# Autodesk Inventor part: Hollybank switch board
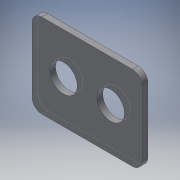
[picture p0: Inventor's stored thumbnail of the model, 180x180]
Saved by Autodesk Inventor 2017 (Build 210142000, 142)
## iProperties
Created: 2015-12
Part Number: Hollybank switch board
Material: Generic
Document SubType Name: Modeling
Designer: Designer
Density: 1 g/cm^3
Appearance: Default
Author: Designer
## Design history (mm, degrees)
sketch "Sketch1"
  geometry: L1 (-57, 68.367)-(23, 68.367); L2 (33, 58.367)-(33, -21.633); L3 (23, -31.633)-(-57, -31.633); L4 (-67, -21.633)-(-67, 58.367); L5 (-5, -5)-(-5, 5.367); L6 (-2, 8.367)-(5, 8.367); L7 (8, 11.367)-(8, 33.367); L8 (-39.45, 36.367)-(5, 36.367); L9 (-36.434, 15.879)-(-43.759, 10.649); L10 (-36.443, 20.769)-(-43.792, 25.973); L11 (-40, 13.333)-(-40, 13.33); L12 (-30.528, -8)-(-8, -8); L13 (188, 148.367)-(-72, 148.367); L14 (-112, 108.367)-(-112, -71.633); L15 (-72, -111.633)-(188, -111.633); L16 (228, -71.633)-(228, 108.367); L17 (188, 148.367)-(228, 148.367); L18 (228, 108.367)-(228, 148.367); L19 (228, -71.633)-(228, -111.633); L20 (183, -111.633)-(228, -111.633); L21 (-72, -111.633)-(-112, -111.633); L22 (-112, -111.633)-(-112, -71.633); L23 (-72, 148.367)-(-112, 148.367); L24 (-112, 108.367)-(-112, 148.367); L25 (109.566, 15.879)-(102.241, 10.649); L26 (154, 11.367)-(154, 33.367); L27 (115.472, -8)-(138, -8); L28 (179, 58.367)-(179, -21.633); L29 (169, -31.633)-(89, -31.633); L30 (106, 13.333)-(106, 13.33); L31 (141, -5)-(141, 5.367); L32 (144, 8.367)-(151, 8.367); L33 (89, 68.367)-(169, 68.367); L34 (106.55, 36.367)-(151, 36.367); L35 (79, -21.633)-(79, 58.367); L36 (109.557, 20.769)-(102.208, 25.973); C1 r 1.5 at (-14.993, 41.367); C2 r 1.5 at (-40, 18.33); C3 r 1.5 at (0, 0); C4 r 1.5 at (106, 18.33); C5 r 1.5 at (146, 0); C6 r 1.5 at (131.007, 41.367); A1 r 30 centre (-17, 18.367) between (-41.944, 35.033) and (-44.842, 29.539); A2 r 30 centre (-17, 18.367) between (-44.795, 7.079) and (-32.031, -7.596); A3 r 10 centre (-57, 58.367) between (-57, 68.367) and (-67, 58.367); A4 r 10 centre (23, 58.367) between (33, 58.367) and (23, 68.367); A5 r 10 centre (23, -21.633) between (23, -31.633) and (33, -21.633); A6 r 10 centre (-57, -21.633) between (-67, -21.633) and (-57, -31.633); A7 r 3 centre (-38.177, 18.321) between (-36.434, 15.879) and (-36.443, 20.769); A8 r 3 centre (5, 11.367) between (5, 8.367) and (8, 11.367); A9 r 3 centre (-2, 5.367) between (-2, 8.367) and (-5, 5.367); A10 r 3 centre (-8, -5) between (-8, -8) and (-5, -5); A11 r 3 centre (-42.016, 8.208) between (-43.759, 10.649) and (-44.795, 7.079); A12 r 3 centre (-42.058, 28.422) between (-44.842, 29.539) and (-43.792, 25.973); A13 r 3 centre (-39.45, 33.367) between (-39.45, 36.367) and (-41.944, 35.033); A14 r 3 centre (-30.528, -5) between (-32.031, -7.596) and (-30.528, -8); A15 r 3 centre (5, 33.367) between (8, 33.367) and (5, 36.367); A16 r 30 centre (129, 18.367) between (101.205, 7.079) and (113.969, -7.596); A17 r 3 centre (138, -5) between (138, -8) and (141, -5); A18 r 3 centre (144, 5.367) between (144, 8.367) and (141, 5.367); A19 r 3 centre (151, 11.367) between (151, 8.367) and (154, 11.367); A20 r 10 centre (169, -21.633) between (169, -31.633) and (179, -21.633); A21 r 10 centre (89, -21.633) between (79, -21.633) and (89, -31.633); A22 r 3 centre (151, 33.367) between (154, 33.367) and (151, 36.367); A23 r 10 centre (169, 58.367) between (179, 58.367) and (169, 68.367); A24 r 10 centre (89, 58.367) between (89, 68.367) and (79, 58.367); A25 r 30 centre (129, 18.367) between (104.056, 35.033) and (101.158, 29.539); A26 r 3 centre (115.472, -5) between (113.969, -7.596) and (115.472, -8); A27 r 3 centre (103.984, 8.208) between (102.241, 10.649) and (101.205, 7.079); A28 r 3 centre (107.823, 18.321) between (109.566, 15.879) and (109.557, 20.769); A29 r 3 centre (103.942, 28.422) between (101.158, 29.539) and (102.208, 25.973); A30 r 3 centre (106.55, 33.367) between (106.55, 36.367) and (104.056, 35.033); 24 further points
  constraints: 72 end point, 68 point on circle, 48 tangent, 46 point on line, 36 centre point, 18 equal radius, 16 perpendicular, 7 equal length, 4 horizontal, 2 coincident
  dimensions: "d4" = 3 diameter of C2; "d5" = 3 diameter of C1; "d7" = 100 distance of point (-67, -31.633) point (-67, 68.367); "d8" = 100 distance of point (-67, 68.367) point (33, 68.367); "d17" = 5 distance from line of point (0, 0) L5; "d19" = 25 distance between parallel lines of L2 L7; "d23" = 34 distance of C1.centre C2.centre; "d24" = 44 distance of C1.centre C3.centre; "d25" = 44 distance of point (0, 0) C2.centre; "d26" = 32 distance between parallel lines of L8 L1; "d27" = 47.99344 distance from line of L2 C1.centre; "d28" = 33 distance from line of L2 point (0, 0); "d29" = 27 distance from line of C2.centre L4 (derived); "d30" = 49.96369 distance from line of L3 C2.centre; "d31" = 31.63338 distance from line of L3 C3.centre (derived); "d32" = 30 radius of A2; "d33" = 30 radius of A1; "d34" = 41 distance from line of L7 point (-33, 18.33); "d35" = 8 distance from line of L12 point (0, 0); "d36" = 23.63338 distance between parallel lines of L3 L12 (derived); "d37" = 10 radius of A3; "d40" = 3 radius of A7; "d41" = 3 radius of A8; "d42" = 3 radius of A15; "d61" = 24.98415 distance from line of L4 A11.centre; "d62" = 39.84089 distance from line of L3 A11.centre; "d63" = 28.82318 distance from line of L4 A7.centre; "d64" = 49.95389 distance from line of L3 A7.centre; "d65" = 27.55006 distance from line of L4 A13.centre; "d66" = 28 distance from line of L2 A15.centre; "d67" = 35 distance from line of A15.centre L1; "d68" = 3 diameter of C3; "d69" = 340 distance of L17.end L23.end; "d70" = 260 distance of L19.end L17.end; "d72" = 45 distance between parallel lines of L14 L4; "d117" = 28 distance from line of L2 A8.centre (derived); "d118" = 43 distance from line of L3 A8.centre; "d119" = 3 diameter of C4; "d120" = 3 diameter of C6; "d121" = 100 distance of point (79, -31.633) point (79, 68.367); "d122" = 100 distance of point (79, 68.367) point (179, 68.367); "d123" = 5 distance from line of point (146, 0) L31; "d124" = 25 distance between parallel lines of L28 L26; "d125" = 34 distance of C6.centre C4.centre; "d126" = 44 distance of C6.centre C5.centre; "d127" = 44 distance of point (146, 0) C4.centre; "d128" = 32 distance between parallel lines of L34 L33; "d129" = 47.99344 distance from line of L28 C6.centre; "d130" = 33 distance from line of L28 point (146, 0); "d131" = 27 distance from line of C4.centre L35 (derived); "d132" = 49.96369 distance from line of L29 C4.centre; "d133" = 31.63338 distance from line of L29 C5.centre (derived); "d134" = 30 radius of A16; "d135" = 30 radius of A25; "d136" = 41 distance from line of L26 point (113, 18.33); "d137" = 8 distance from line of L27 point (146, 0); "d138" = 23.63338 distance between parallel lines of L29 L27 (derived); "d139" = 10 radius of A24; "d140" = 3 radius of A28; "d141" = 3 radius of A19; "d142" = 3 radius of A22; "d143" = 24.98415 distance from line of L35 A27.centre; "d144" = 39.84089 distance from line of L29 A27.centre; "d145" = 28.82318 distance from line of L35 A28.centre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
extrude "Extrusion10" new body sketch "Sketch1" distance "d161" = 30; taper "d162" = 0 deg
sketch "Sketch6"
  geometry: L1 (-131.007, 41.367)-(-131.007, 10.217); L2 (14.993, 41.367)-(14.993, 11.919); L3 (112, 148.367)-(112, -111.633) reference; L4 (-131.007, 18.33)-(40, 18.33); C1 r 1.5 at (-131.007, 41.367) reference; C2 r 1.5 at (14.993, 41.367) reference; C3 r 1.5 at (40, 18.33) reference; C4 r 42.5 at (-131.007, 18.33); C5 r 42.5 at (14.993, 18.33); 1 further point
  constraints: 6 end point, 3 point on line, 2 centre point, 2 vertical, 1 coincident, 1 horizontal
  dimensions: "d164" = 85 diameter of C4; "d165" = 85 diameter of C5
extrude "Extrusion11" cut sketch "Sketch6" distance "d166" = 24; taper "d167" = 0 deg
fillet "Fillet1" dims "d168" = 30
sketch "Sketch7"
  geometry: L1 (324.857, 18)-(-75.143, 18); L2 (-75.143, 18)-(-75.143, 38); L3 (-75.143, 38)-(324.857, 38); L4 (324.857, 38)-(324.857, 18); L5 (0, 30)-(280, 30) reference; 1 further point
  constraints: 8 end point, 2 parallel, 1 horizontal, 1 perpendicular
  dimensions: "d169" = 20 distance of L3.end L1.start; "d170" = 400 distance of L1.start L1.end; "d174" = 12 distance between parallel lines of L5 L1
extrude "Extrusion12" cut sketch "Sketch7" stored distance "d172" = 24; taper "d173" = 0 deg
body "Solid4"
other parameters: "d15" = 32, "d16" = 25
